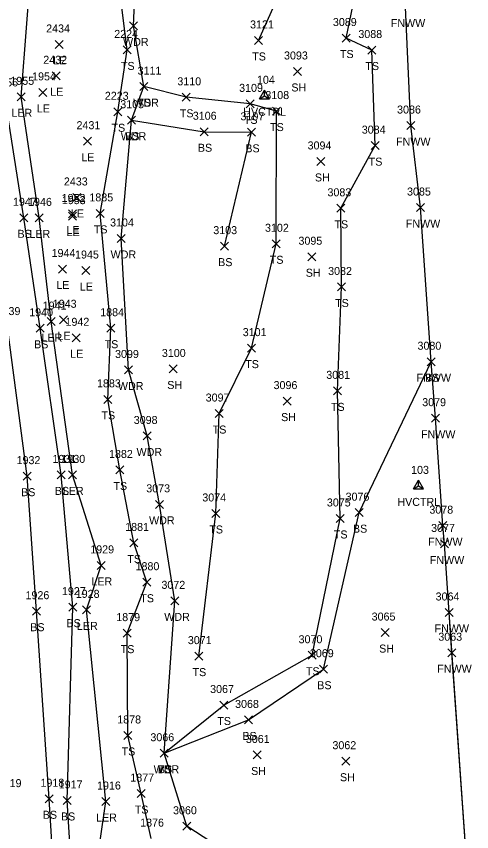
# Model space of a CAD drawing. Extents: x 1650221 to 1650634, y 244606 to 249996.
# Drawn here: x 1650471.2 to 1650585.1, y 245132.2 to 245336 of the extents above; entities that cross this region are included whole.
import ezdxf

# ---------------------------------------------------------------- set-up
doc = ezdxf.new("R2010")
doc.units = 0
for name, color, linetype in [('C_A', 7, 'Continuous'), ('C_I', 7, 'Continuous'), ('CPSM', 7, 'Continuous'), ('L_A', 7, 'Continuous'), ('L_I', 7, 'Continuous'), ('L_TIC', 7, 'Continuous'), ('LARO', 7, 'Continuous'), ('LAWA', 7, 'Continuous'), ('LELB', 7, 'Continuous'), ('LFNC', 7, 'Continuous'), ('LSOGP', 7, 'Continuous')]:
    doc.layers.add(name, color=color, linetype=linetype)

msp = doc.modelspace()

# ---------------------------------------------------------------- linework, layer by layer
at = {"layer": 'CPSM'}
for p, q in [((1650532.02, 245315.4), (1650533.27, 245317.56)), ((1650534.52, 245315.4), (1650533.27, 245317.56)), ((1650533.27, 245316.12), (1650533.27, 245317.56)), ((1650532.02, 245315.4), (1650533.27, 245316.12)), ((1650532.02, 245315.4), (1650534.52, 245315.4)), ((1650533.27, 245316.12), (1650533.27, 245316.12)), ((1650533.27, 245316.12), (1650534.52, 245315.4)), ((1650570.55, 245217.89), (1650571.8, 245220.06)), ((1650573.05, 245217.89), (1650571.8, 245220.06)), ((1650571.8, 245218.62), (1650571.8, 245220.06)), ((1650570.55, 245217.89), (1650571.8, 245218.62)), ((1650570.55, 245217.89), (1650573.05, 245217.89)), ((1650571.8, 245218.62), (1650571.8, 245218.62)), ((1650571.8, 245218.62), (1650573.05, 245217.89))]:
    msp.add_line(p, q, dxfattribs=at)
at = {"layer": 'L_TIC'}
for points in [[(1650499.57, 245332.59), (1650501.57, 245334.59)], [(1650501.57, 245332.59), (1650499.57, 245334.59)], [(1650530.8, 245328.95), (1650532.8, 245330.95)], [(1650532.8, 245328.95), (1650530.8, 245330.95)], [(1650552.73, 245329.55), (1650554.73, 245331.55)], [(1650554.73, 245329.55), (1650552.73, 245331.55)], [(1650480.97, 245327.95), (1650482.97, 245329.95)], [(1650482.97, 245327.95), (1650480.97, 245329.95)], [(1650497.98, 245326.58), (1650499.98, 245328.58)], [(1650499.98, 245326.58), (1650497.98, 245328.58)], [(1650559.08, 245326.55), (1650561.08, 245328.55)], [(1650561.08, 245326.55), (1650559.08, 245328.55)], [(1650540.5, 245321.2), (1650542.5, 245323.2)], [(1650542.5, 245321.2), (1650540.5, 245323.2)], [(1650480.25, 245320.12), (1650482.25, 245322.12)], [(1650482.25, 245320.12), (1650480.25, 245322.12)], [(1650502.12, 245317.4), (1650504.12, 245319.4)], [(1650504.12, 245317.4), (1650502.12, 245319.4)], [(1650502.12, 245317.4), (1650504.12, 245319.4)], [(1650504.12, 245317.4), (1650502.12, 245319.4)], [(1650471.44, 245314.86), (1650473.44, 245316.86)], [(1650473.44, 245314.86), (1650471.44, 245316.86)], [(1650476.9, 245315.97), (1650478.9, 245317.97)], [(1650478.9, 245315.97), (1650476.9, 245317.97)], [(1650512.71, 245314.74), (1650514.71, 245316.74)], [(1650514.71, 245314.74), (1650512.71, 245316.74)], [(1650528.72, 245313.1), (1650530.72, 245315.1)], [(1650530.72, 245313.1), (1650528.72, 245315.1)], [(1650495.63, 245311.12), (1650497.63, 245313.12)], [(1650497.63, 245311.12), (1650495.63, 245313.12)], [(1650535.26, 245311.3), (1650537.26, 245313.3)], [(1650537.26, 245311.3), (1650535.26, 245313.3)], [(1650499, 245309.02), (1650501, 245311.02)], [(1650501, 245309.02), (1650499, 245311.02)], [(1650499, 245309.02), (1650501, 245311.02)], [(1650501, 245309.02), (1650499, 245311.02)], [(1650568.82, 245307.68), (1650570.82, 245309.68)], [(1650570.82, 245307.68), (1650568.82, 245309.68)], [(1650517.19, 245306.13), (1650519.19, 245308.13)], [(1650519.19, 245306.13), (1650517.19, 245308.13)], [(1650529.05, 245305.99), (1650531.05, 245307.99)], [(1650531.05, 245305.99), (1650529.05, 245307.99)], [(1650529.05, 245305.99), (1650531.05, 245307.99)], [(1650531.05, 245305.99), (1650529.05, 245307.99)], [(1650488, 245303.77), (1650490, 245305.77)], [(1650490, 245303.77), (1650488, 245305.77)], [(1650559.92, 245302.66), (1650561.92, 245304.66)], [(1650561.92, 245302.66), (1650559.92, 245304.66)], [(1650546.39, 245298.71), (1650548.39, 245300.71)], [(1650548.39, 245298.71), (1650546.39, 245300.71)], [(1650485.4, 245289.71), (1650487.4, 245291.71)], [(1650487.4, 245289.71), (1650485.4, 245291.71)], [(1650551.36, 245287), (1650553.36, 245289)], [(1650553.36, 245287), (1650551.36, 245289)], [(1650571.25, 245287.19), (1650573.25, 245289.19)], [(1650573.25, 245287.19), (1650571.25, 245289.19)], [(1650472.1, 245284.62), (1650474.1, 245286.62)], [(1650474.1, 245284.62), (1650472.1, 245286.62)], [(1650475.93, 245284.6), (1650477.93, 245286.6)], [(1650477.93, 245284.6), (1650475.93, 245286.6)], [(1650484.27, 245285.58), (1650486.27, 245287.58)], [(1650486.27, 245285.58), (1650484.27, 245287.58)], [(1650484.32, 245285.04), (1650486.32, 245287.04)], [(1650486.32, 245285.04), (1650484.32, 245287.04)], [(1650491.2, 245285.73), (1650493.2, 245287.73)], [(1650493.2, 245285.73), (1650491.2, 245287.73)], [(1650496.45, 245279.46), (1650498.45, 245281.46)], [(1650498.45, 245279.46), (1650496.45, 245281.46)], [(1650535.19, 245278.13), (1650537.19, 245280.13)], [(1650537.19, 245278.13), (1650535.19, 245280.13)], [(1650522.25, 245277.54), (1650524.25, 245279.54)], [(1650524.25, 245277.54), (1650522.25, 245279.54)], [(1650544.11, 245274.89), (1650546.11, 245276.89)], [(1650546.11, 245274.89), (1650544.11, 245276.89)], [(1650481.77, 245271.82), (1650483.77, 245273.82)], [(1650483.77, 245271.82), (1650481.77, 245273.82)], [(1650487.62, 245271.45), (1650489.62, 245273.45)], [(1650489.62, 245271.45), (1650487.62, 245273.45)], [(1650551.52, 245267.33), (1650553.52, 245269.33)], [(1650553.52, 245267.33), (1650551.52, 245269.33)], [(1650478.96, 245258.68), (1650480.96, 245260.68)], [(1650480.96, 245258.68), (1650478.96, 245260.68)], [(1650482.05, 245259.14), (1650484.05, 245261.14)], [(1650484.05, 245259.14), (1650482.05, 245261.14)], [(1650476.25, 245257), (1650478.25, 245259)], [(1650478.25, 245257), (1650476.25, 245259)], [(1650493.91, 245257.03), (1650495.91, 245259.03)], [(1650495.91, 245257.03), (1650493.91, 245259.03)], [(1650485.23, 245254.63), (1650487.23, 245256.63)], [(1650487.23, 245254.63), (1650485.23, 245256.63)], [(1650529.05, 245252.05), (1650531.05, 245254.05)], [(1650531.05, 245252.05), (1650529.05, 245254.05)], [(1650573.95, 245248.65), (1650575.95, 245250.65)], [(1650575.95, 245248.65), (1650573.95, 245250.65)], [(1650573.95, 245248.65), (1650575.95, 245250.65)], [(1650575.95, 245248.65), (1650573.95, 245250.65)], [(1650498.28, 245246.59), (1650500.28, 245248.59)], [(1650500.28, 245246.59), (1650498.28, 245248.59)], [(1650509.49, 245246.84), (1650511.49, 245248.84)], [(1650511.49, 245246.84), (1650509.49, 245248.84)], [(1650550.49, 245241.37), (1650552.49, 245243.37)], [(1650552.49, 245241.37), (1650550.49, 245243.37)], [(1650493.12, 245239.25), (1650495.12, 245241.25)], [(1650495.12, 245239.25), (1650493.12, 245241.25)], [(1650537.94, 245238.81), (1650539.94, 245240.81)], [(1650539.94, 245238.81), (1650537.94, 245240.81)], [(1650520.92, 245235.7), (1650522.92, 245237.7)], [(1650522.92, 245235.7), (1650520.92, 245237.7)], [(1650575.05, 245234.54), (1650577.05, 245236.54)], [(1650577.05, 245234.54), (1650575.05, 245236.54)], [(1650502.94, 245230.1), (1650504.94, 245232.1)], [(1650504.94, 245230.1), (1650502.94, 245232.1)], [(1650496.12, 245221.6), (1650498.12, 245223.6)], [(1650498.12, 245221.6), (1650496.12, 245223.6)], [(1650473, 245220.05), (1650475, 245222.05)], [(1650475, 245220.05), (1650473, 245222.05)], [(1650481.43, 245220.37), (1650483.43, 245222.37)], [(1650483.43, 245220.37), (1650481.43, 245222.37)], [(1650484.3, 245220.37), (1650486.3, 245222.37)], [(1650486.3, 245220.37), (1650484.3, 245222.37)], [(1650506.07, 245213.01), (1650508.07, 245215.01)], [(1650508.07, 245213.01), (1650506.07, 245215.01)], [(1650520.08, 245210.73), (1650522.08, 245212.73)], [(1650522.08, 245210.73), (1650520.08, 245212.73)], [(1650555.95, 245210.93), (1650557.95, 245212.93)], [(1650557.95, 245210.93), (1650555.95, 245212.93)], [(1650551.21, 245209.48), (1650553.21, 245211.48)], [(1650553.21, 245209.48), (1650551.21, 245211.48)], [(1650576.83, 245207.68), (1650578.83, 245209.68)], [(1650578.83, 245207.68), (1650576.83, 245209.68)], [(1650499.59, 245203.36), (1650501.59, 245205.36)], [(1650501.59, 245203.36), (1650499.59, 245205.36)], [(1650577.26, 245203.11), (1650579.26, 245205.11)], [(1650579.26, 245203.11), (1650577.26, 245205.11)], [(1650491.44, 245197.75), (1650493.44, 245199.75)], [(1650493.44, 245197.75), (1650491.44, 245199.75)], [(1650502.83, 245193.54), (1650504.83, 245195.54)], [(1650504.83, 245193.54), (1650502.83, 245195.54)], [(1650509.86, 245188.89), (1650511.86, 245190.89)], [(1650511.86, 245188.89), (1650509.86, 245190.89)], [(1650475.29, 245186.3), (1650477.29, 245188.3)], [(1650477.29, 245186.3), (1650475.29, 245188.3)], [(1650484.34, 245187.31), (1650486.34, 245189.31)], [(1650486.34, 245187.31), (1650484.34, 245189.31)], [(1650487.81, 245186.64), (1650489.81, 245188.64)], [(1650489.81, 245186.64), (1650487.81, 245188.64)], [(1650578.44, 245185.98), (1650580.44, 245187.98)], [(1650580.44, 245185.98), (1650578.44, 245187.98)], [(1650497.93, 245180.82), (1650499.93, 245182.82)], [(1650499.93, 245180.82), (1650497.93, 245182.82)], [(1650562.45, 245180.96), (1650564.45, 245182.96)], [(1650564.45, 245180.96), (1650562.45, 245182.96)], [(1650515.9, 245175.07), (1650517.9, 245177.07)], [(1650517.9, 245175.07), (1650515.9, 245177.07)], [(1650544.23, 245175.29), (1650546.23, 245177.29)], [(1650546.23, 245175.29), (1650544.23, 245177.29)], [(1650579.12, 245175.92), (1650581.12, 245177.92)], [(1650581.12, 245175.92), (1650579.12, 245177.92)], [(1650547.03, 245171.8), (1650549.03, 245173.8)], [(1650549.03, 245171.8), (1650547.03, 245173.8)], [(1650522.08, 245162.85), (1650524.08, 245164.85)], [(1650524.08, 245162.85), (1650522.08, 245164.85)], [(1650528.32, 245159.12), (1650530.32, 245161.12)], [(1650530.32, 245159.12), (1650528.32, 245161.12)], [(1650498.16, 245155.24), (1650500.16, 245157.24)], [(1650500.16, 245155.24), (1650498.16, 245157.24)], [(1650507.2, 245150.8), (1650509.2, 245152.8)], [(1650509.2, 245150.8), (1650507.2, 245152.8)], [(1650507.2, 245150.8), (1650509.2, 245152.8)], [(1650509.2, 245150.8), (1650507.2, 245152.8)], [(1650507.2, 245150.8), (1650509.2, 245152.8)], [(1650509.2, 245150.8), (1650507.2, 245152.8)], [(1650530.44, 245150.37), (1650532.44, 245152.37)], [(1650532.44, 245150.37), (1650530.44, 245152.37)], [(1650552.65, 245148.81), (1650554.65, 245150.81)], [(1650554.65, 245148.81), (1650552.65, 245150.81)], [(1650478.42, 245139.42), (1650480.42, 245141.42)], [(1650480.42, 245139.42), (1650478.42, 245141.42)], [(1650501.44, 245140.72), (1650503.44, 245142.72)], [(1650503.44, 245140.72), (1650501.44, 245142.72)], [(1650482.97, 245139), (1650484.97, 245141)], [(1650484.97, 245139), (1650482.97, 245141)], [(1650492.61, 245138.73), (1650494.61, 245140.73)], [(1650494.61, 245138.73), (1650492.61, 245140.73)], [(1650512.9, 245132.55), (1650514.9, 245134.55)], [(1650514.9, 245132.55), (1650512.9, 245134.55)], [(1650512.9, 245132.55), (1650514.9, 245134.55)], [(1650514.9, 245132.55), (1650512.9, 245134.55)]]:
    msp.add_lwpolyline(points, dxfattribs=at)
at = {"layer": 'LARO'}
msp.add_lwpolyline([(1650491, 245121.86), (1650493.61, 245139.73), (1650488.81, 245187.64), (1650492.44, 245198.75), (1650485.3, 245221.37), (1650479.96, 245259.68), (1650476.93, 245285.6), (1650472.44, 245315.86), (1650475.26, 245352.64), (1650477.44, 245377.75), (1650471.06, 245430.31), (1650471.03, 245462.47), (1650469.65, 245517.3), (1650470.03, 245548.03), (1650459.64, 245596.52), (1650458.35, 245631.93), (1650449.5, 245684.33)], dxfattribs=at)
at = {"layer": 'LAWA'}
msp.add_lwpolyline([(1650513.9, 245133.55), (1650508.2, 245151.8), (1650510.86, 245189.89), (1650507.07, 245214.01), (1650503.94, 245231.1), (1650499.28, 245247.59), (1650497.45, 245280.46), (1650500, 245310.02), (1650503.12, 245318.4), (1650500.57, 245333.59), (1650501.31, 245350.82), (1650505.94, 245377.88), (1650508.67, 245396.66), (1650507.35, 245410.21), (1650510.12, 245425.89), (1650505.4, 245439.37), (1650500.44, 245467.37)], dxfattribs=at)
at = {"layer": 'LELB'}
for points in [[(1650489.71, 244991.22), (1650489.69, 245009.71), (1650486.09, 245047.64), (1650483.87, 245079.25), (1650480.92, 245116.18), (1650479.42, 245140.42), (1650476.29, 245187.3), (1650474, 245221.05), (1650469.02, 245258.31), (1650465.71, 245285.05), (1650462.26, 245315.54), (1650460.48, 245356.55), (1650462.16, 245378.82), (1650455.67, 245427.55), (1650451.48, 245462.76), (1650449.79, 245512.44), (1650449.11, 245548.12), (1650443.42, 245590.47), (1650442.32, 245632.05), (1650435.43, 245684.43)], [(1650504.95, 245130.46), (1650502.44, 245141.72), (1650499.16, 245156.24), (1650498.93, 245181.82), (1650503.83, 245194.54), (1650500.59, 245204.36), (1650497.12, 245222.6), (1650494.12, 245240.25), (1650494.91, 245258.03), (1650492.2, 245286.73), (1650496.63, 245312.12), (1650498.98, 245327.58), (1650495.95, 245351.61), (1650501.94, 245378.34), (1650498.52, 245407), (1650497.68, 245445.99), (1650496.14, 245475.39), (1650481.11, 245501.15), (1650483.43, 245539.97), (1650491.3, 245600.05), (1650490.9, 245637.99), (1650484.15, 245671.67)], [(1650493.15, 245007.74), (1650488.13, 245047.67), (1650486.59, 245079.09), (1650485.35, 245117.44), (1650483.97, 245140), (1650485.34, 245188.31), (1650482.43, 245221.37), (1650477.25, 245258), (1650473.1, 245285.62), (1650468.47, 245315.46), (1650468.65, 245355.64), (1650472.97, 245377.88), (1650463.98, 245429.04), (1650464.45, 245462.11), (1650460.79, 245514.67), (1650465.46, 245547.92), (1650447.43, 245596.3), (1650450.46, 245632.25)], [(1650531.8, 245329.95), (1650539.4, 245346.94), (1650542.05, 245366.48), (1650535.76, 245393.23), (1650531.72, 245411.6), (1650544.91, 245426.88), (1650553.84, 245468.57), (1650557.53, 245481.22)], [(1650508.2, 245151.8), (1650523.08, 245163.85), (1650545.23, 245176.29), (1650552.21, 245210.48), (1650551.49, 245242.37), (1650552.52, 245268.33), (1650552.36, 245288), (1650560.92, 245303.66), (1650560.08, 245327.55), (1650553.73, 245330.55), (1650558.47, 245353.42), (1650566.12, 245367.99)], [(1650516.9, 245176.07), (1650521.08, 245211.73), (1650521.92, 245236.7), (1650530.05, 245253.05), (1650536.19, 245279.13), (1650536.26, 245312.3), (1650529.72, 245314.1), (1650513.71, 245315.74), (1650503.12, 245318.4)], [(1650500, 245310.02), (1650518.19, 245307.13), (1650530.05, 245306.99)], [(1650523.25, 245278.54), (1650530.05, 245306.99)], [(1650508.2, 245151.8), (1650529.32, 245160.12), (1650548.03, 245172.8), (1650556.95, 245211.93), (1650574.95, 245249.65)], [(1650516.47, 245084.32), (1650525.56, 245101.01), (1650524.17, 245126.86), (1650513.9, 245133.55)]]:
    msp.add_lwpolyline(points, dxfattribs=at)
at = {"layer": 'LFNC'}
msp.add_lwpolyline([(1650584.33, 245116.87), (1650580.12, 245176.92), (1650579.44, 245186.98), (1650578.26, 245204.11), (1650577.83, 245208.68), (1650576.05, 245235.54), (1650574.95, 245249.65), (1650572.25, 245288.19), (1650569.82, 245308.68), (1650568.5, 245338.31), (1650566.12, 245367.99), (1650564.63, 245386.6), (1650563.27, 245407.82), (1650561.55, 245428.25), (1650560.06, 245447.86), (1650559.29, 245459.19), (1650557.53, 245481.22)], dxfattribs=at)
at = {"layer": 'LSOGP'}
msp.add_lwpolyline([(1650584.33, 245116.87), (1650579.44, 245186.98), (1650578.26, 245204.11), (1650577.83, 245208.68), (1650576.05, 245235.54), (1650574.95, 245249.65), (1650572.25, 245288.19), (1650569.82, 245308.68), (1650568.5, 245338.31), (1650566.12, 245367.99), (1650564.63, 245386.6), (1650563.27, 245407.82), (1650561.55, 245428.25), (1650560.06, 245447.86), (1650559.29, 245459.19), (1650557.53, 245481.22)], dxfattribs=at)

# ---------------------------------------------------------------- texts
at = {"layer": 'C_A'}
for p in [(1650527.97, 245311.12), (1650566.49, 245213.62)]:
    msp.add_text('HVCTRL', height=2, dxfattribs=at).set_placement(p)
at = {"layer": 'C_I'}
for s, p in [('104', (1650531.4, 245319.12)), ('103', (1650569.92, 245221.62))]:
    msp.add_text(s, height=2, dxfattribs=at).set_placement(p)
at = {"layer": 'L_A'}
for s, p in [('FNWW', (1650564.85, 245333.31)), ('WDR', (1650497.93, 245328.59)), ('TS', (1650530.21, 245324.95)), ('TS', (1650552.14, 245325.55)), ('LE', (1650480.46, 245323.95)), ('TS', (1650497.39, 245322.58)), ('TS', (1650558.49, 245322.55)), ('SH', (1650539.99, 245317.2)), ('LE', (1650479.74, 245316.12)), ('WDR', (1650500.48, 245313.4)), ('TS', (1650501.53, 245313.4)), ('LER', (1650470.02, 245310.86)), ('LE', (1650476.38, 245311.97)), ('TS', (1650512.12, 245310.74)), ('TS', (1650528.13, 245309.1)), ('TS', (1650495.04, 245307.12)), ('TS', (1650534.67, 245307.3)), ('WDR', (1650497.36, 245305.02)), ('BS', (1650498.44, 245305.02)), ('FNWW', (1650566.16, 245303.68)), ('BS', (1650516.63, 245302.13)), ('BS', (1650528.49, 245301.99)), ('BS', (1650528.49, 245301.99)), ('LE', (1650487.49, 245299.77)), ('TS', (1650559.33, 245298.66)), ('SH', (1650545.88, 245294.71)), ('LE', (1650484.89, 245285.71)), ('TS', (1650550.77, 245283)), ('FNWW', (1650568.6, 245283.19)), ('BS', (1650471.54, 245280.62)), ('LER', (1650474.52, 245280.6)), ('LE', (1650483.76, 245281.58)), ('LE', (1650483.81, 245281.04)), ('TS', (1650490.61, 245281.73)), ('WDR', (1650494.81, 245275.46)), ('TS', (1650534.6, 245274.13)), ('BS', (1650521.69, 245273.54)), ('SH', (1650543.6, 245270.89)), ('LE', (1650481.25, 245267.82)), ('LE', (1650487.11, 245267.45)), ('TS', (1650550.93, 245263.33)), ('LER', (1650477.54, 245254.68)), ('LE', (1650481.54, 245255.14)), ('BS', (1650475.69, 245253)), ('TS', (1650493.32, 245253.03)), ('LE', (1650484.72, 245250.63)), ('TS', (1650528.46, 245248.05)), ('FNWW', (1650571.29, 245244.65)), ('BS', (1650573.39, 245244.65)), ('WDR', (1650496.64, 245242.59)), ('SH', (1650508.98, 245242.84)), ('TS', (1650549.9, 245237.37)), ('TS', (1650492.53, 245235.25)), ('SH', (1650537.43, 245234.81)), ('TS', (1650520.33, 245231.7)), ('FNWW', (1650572.39, 245230.54)), ('WDR', (1650501.3, 245226.1)), ('TS', (1650495.53, 245217.6)), ('BS', (1650472.44, 245216.05)), ('BS', (1650480.87, 245216.37)), ('LER', (1650482.88, 245216.37)), ('WDR', (1650504.43, 245209.01)), ('TS', (1650519.49, 245206.73)), ('BS', (1650555.39, 245206.93)), ('TS', (1650550.62, 245205.48)), ('FNWW', (1650574.17, 245203.68)), ('TS', (1650499, 245199.36)), ('FNWW', (1650574.6, 245199.11)), ('LER', (1650490.02, 245193.75)), ('TS', (1650502.24, 245189.54)), ('WDR', (1650508.22, 245184.89)), ('BS', (1650474.74, 245182.3)), ('BS', (1650483.78, 245183.31)), ('LER', (1650486.39, 245182.64)), ('FNWW', (1650575.78, 245181.98)), ('TS', (1650497.34, 245176.82)), ('SH', (1650561.94, 245176.96)), ('TS', (1650515.3, 245171.07)), ('TS', (1650543.64, 245171.29)), ('FNWW', (1650576.46, 245171.92)), ('BS', (1650546.47, 245167.8)), ('TS', (1650521.49, 245158.85)), ('BS', (1650527.76, 245155.12)), ('TS', (1650497.57, 245151.24)), ('WDR', (1650505.57, 245146.8)), ('TS', (1650506.61, 245146.8)), ('BS', (1650506.64, 245146.8)), ('SH', (1650529.93, 245146.37)), ('SH', (1650552.14, 245144.81)), ('BS', (1650477.86, 245135.42)), ('TS', (1650500.85, 245136.72)), ('BS', (1650482.41, 245135)), ('LER', (1650491.19, 245134.73))]:
    msp.add_text(s, height=2, dxfattribs=at).set_placement(p)
at = {"layer": 'L_I'}
for s, p in [('3121', (1650529.67, 245332.95)), ('3089', (1650550.38, 245333.55)), ('2434', (1650478.71, 245331.95)), ('2224', (1650495.72, 245330.58)), ('3088', (1650556.74, 245330.55)), ('3093', (1650538.16, 245325.2)), ('2432', (1650477.99, 245324.12)), ('3111', (1650501.56, 245321.4)), ('3111', (1650501.56, 245321.4)), ('1955', (1650469.75, 245318.86)), ('1954', (1650475.2, 245319.97)), ('3110', (1650511.5, 245318.74)), ('1956', (1650465.73, 245318.46)), ('3109', (1650526.94, 245317.1)), ('2223', (1650493.37, 245315.12)), ('3108', (1650533.49, 245315.3)), ('3105', (1650497.23, 245313.02)), ('3105', (1650497.23, 245313.02)), ('3086', (1650566.42, 245311.68)), ('3106', (1650515.36, 245310.13)), ('3107', (1650527.27, 245309.99)), ('3107', (1650527.27, 245309.99)), ('2431', (1650486.3, 245307.77)), ('3084', (1650557.59, 245306.66)), ('3094', (1650544.05, 245302.71)), ('2433', (1650483.14, 245293.71)), ('3083', (1650549.02, 245291)), ('3085', (1650568.91, 245291.19)), ('1947', (1650470.41, 245288.62)), ('1946', (1650474.19, 245288.6)), ('1952', (1650482.58, 245289.58)), ('1953', (1650482.63, 245289.04)), ('1885', (1650489.51, 245289.73)), ('3104', (1650494.68, 245283.46)), ('3102', (1650533.41, 245282.13)), ('3103', (1650520.48, 245281.54)), ('3095', (1650541.77, 245278.89)), ('1944', (1650480.07, 245275.82)), ('1945', (1650485.93, 245275.45)), ('3082', (1650549.18, 245271.33)), ('1941', (1650477.84, 245262.68)), ('1943', (1650480.36, 245263.14)), ('1939', (1650466.32, 245261.31)), ('1940', (1650474.47, 245261)), ('1884', (1650492.22, 245261.03)), ('1942', (1650483.54, 245258.63)), ('3101', (1650527.84, 245256.05)), ('3080', (1650571.52, 245252.65)), ('3080', (1650571.52, 245252.65)), ('3099', (1650495.93, 245250.59)), ('3100', (1650507.63, 245250.84)), ('3081', (1650548.72, 245245.37)), ('1883', (1650491.42, 245243.25)), ('3096', (1650535.55, 245242.81)), ('3097', (1650518.58, 245239.7)), ('3079', (1650572.7, 245238.54)), ('3098', (1650500.6, 245234.1)), ('1882', (1650494.42, 245225.6)), ('1932', (1650471.31, 245224.05)), ('1931', (1650480.3, 245224.37)), ('1930', (1650482.52, 245224.37)), ('3073', (1650503.73, 245217.01)), ('3076', (1650553.55, 245214.93)), ('3074', (1650517.74, 245214.73)), ('3075', (1650548.87, 245213.48)), ('3078', (1650574.49, 245211.68)), ('1881', (1650498.46, 245207.36)), ('3077', (1650574.92, 245207.11)), ('1929', (1650489.73, 245201.75)), ('1880', (1650501.05, 245197.54)), ('3072', (1650507.52, 245192.89)), ('1926', (1650473.55, 245190.3)), ('1927', (1650482.65, 245191.31)), ('1928', (1650486.11, 245190.64)), ('3064', (1650576.05, 245189.98)), ('1879', (1650496.23, 245184.82)), ('3065', (1650560.06, 245184.96)), ('3071', (1650514.12, 245179.07)), ('3070', (1650541.8, 245179.29)), ('3063', (1650576.73, 245179.92)), ('3069', (1650544.63, 245175.8)), ('3067', (1650519.69, 245166.85)), ('3068', (1650525.93, 245163.12)), ('1878', (1650496.47, 245159.24)), ('3066', (1650504.76, 245154.8)), ('3066', (1650504.76, 245154.8)), ('3066', (1650504.76, 245154.8)), ('3061', (1650528.62, 245154.37)), ('3062', (1650550.26, 245152.81)), ('1918', (1650477.29, 245143.42)), ('1877', (1650499.75, 245144.72)), ('1919', (1650466.6, 245143.33)), ('1917', (1650481.85, 245143)), ('1916', (1650491.43, 245142.73)), ('3060', (1650510.42, 245136.55)), ('3060', (1650510.42, 245136.55)), ('1876', (1650502.2, 245133.46))]:
    msp.add_text(s, height=2, dxfattribs=at).set_placement(p)

doc.saveas('drawing.dxf')
